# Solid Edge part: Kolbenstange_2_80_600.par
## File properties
Username: ahadarics
Dokumentum tartalom típus: 0
Author: ahadarics
Last saved by: ahadarics
Revision: 89
Sűrűség: 0,000 kg/m^3
Pontosság: 0,990
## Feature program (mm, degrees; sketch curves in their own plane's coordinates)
base feature "unnamed BaseFeature 1"
thread "unnamed Thread 1"
chamfer "Letörés_1"  SetBackValue2 = 20 deg
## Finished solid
Body 1: solid body, 19 faces, 31 edges, 16 vertices.
  Faces by surface: plane 8, cylinder 5, cone 3, torus 3
  Edges by curve: circle 18, line 8, curve on surface 3, ellipse 2
Bounding box of the edges (mm; curved faces can reach further): 80.000 x 80.000 x 727.000, from (-40, -40, -76) to (40, 40, 651).
Cylindrical faces by radius (mm): R8.75 x1, R10 x1, R12.25 x1, R12.5 x1, R40 x1
Conical faces (half-angle, radius in mm at the cone's reference point): 20 deg R8.7989 x1, 30 deg R12.375 x1, 60 deg R9.375 x1
Toroidal faces (ring radius, tube radius in mm): R9.15 r0.4 x2, R10.45 r1.8 x1
Planar faces by outward normal: +x 1, +z 3, -x 1, -z 1, oblique 2
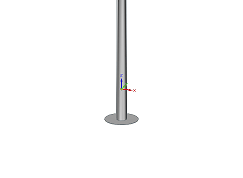
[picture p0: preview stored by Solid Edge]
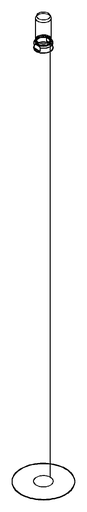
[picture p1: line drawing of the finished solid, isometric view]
